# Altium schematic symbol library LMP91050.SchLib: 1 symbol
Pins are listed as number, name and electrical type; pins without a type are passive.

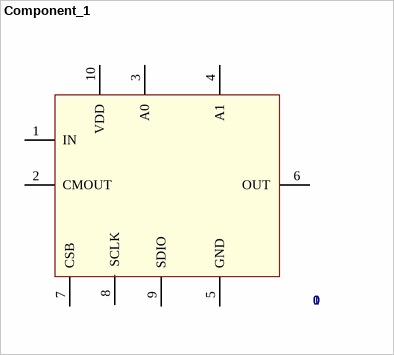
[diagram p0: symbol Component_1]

## Component_1
designator U?, comment LMP91050  NDAC0: 0  NDAC7: 1
simulation model LMP91050 (Model Description)
pins: 1 IN, 2 CMOUT, 3 A0, 4 A1, 5 GND (power), 6 OUT, 7 CSB, 8 SCLK, 9 SDIO, 10 VDD (power)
